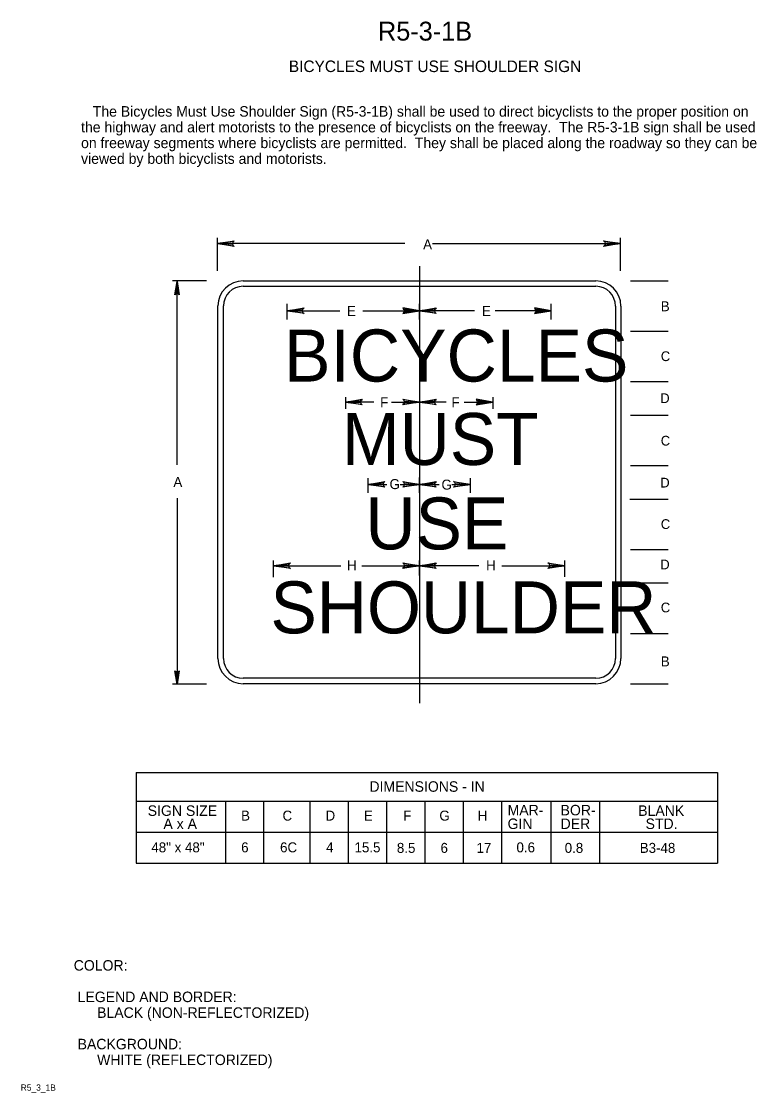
# Model space of a CAD drawing. Extents: x 0.013 to 0.188, y 0.004 to 0.259.
import ezdxf

# ---------------------------------------------------------------- set-up
doc = ezdxf.new("R2010")
doc.units = 0
for name, color, linetype in [('1', 7, 'Continuous'), ('11', 7, 'Continuous'), ('2', 7, 'Continuous'), ('3', 7, 'Continuous')]:
    doc.layers.add(name, color=color, linetype=linetype)

# ---------------------------------------------------------------- blocks, each defined once
blk = doc.blocks.new('RARROW')
at = {"layer": '3'}
for p, q in [((-2.156, 0.28500000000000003), (-2.2665, 0.384625)), ((-2.2665, 0.384625), (0, 0)), ((0, 0), (-2.2665, -0.379125)), ((-2.156, 0.28500000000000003), (-2.075625, 0.12075)), ((0, 0), (-2.156, 0.28500000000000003)), ((-2.14975, -0.2705), (0, 0)), ((-2.075625, 0.12075), (0, 0)), ((0, 0), (-2.074, -0.108)), ((-2.2665, -0.379125), (-2.14975, -0.2705)), ((-2.074, -0.108), (-2.14975, -0.2705))]:
    blk.add_line(p, q, dxfattribs=at)

msp = doc.modelspace()

# ---------------------------------------------------------------- linework, layer by layer
at = {"layer": '11'}
msp.add_line((0.059375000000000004, 0.107375), (0.059375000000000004, 0.107375), dxfattribs=at)
at = {"layer": '3'}
for p, q in [((0.059375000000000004, 0.19975), (0.059375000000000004, 0.207625)), ((0.155375, 0.19975), (0.155375, 0.207625)), ((0.10400000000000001, 0.20625000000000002), (0.059375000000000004, 0.20625000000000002)), ((0.110625, 0.20625000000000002), (0.155375, 0.20625000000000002)), ((0.1075, 0.200875), (0.1075, 0.09675)), ((0.05675, 0.197375), (0.048625, 0.197375)), ((0.04975, 0.1535), (0.04975, 0.197375)), ((0.06550000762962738, 0.197375), (0.1495, 0.197375)), ((0.15775, 0.197375), (0.16675, 0.197375)), ((0.06550000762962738, 0.19607499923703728), (0.1495, 0.19607499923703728)), ((0.076, 0.18812500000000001), (0.076, 0.19187500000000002)), ((0.1075, 0.18812500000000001), (0.1075, 0.19187500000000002)), ((0.138875, 0.18812500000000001), (0.138875, 0.19187500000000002)), ((0.05950001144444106, 0.107375), (0.05950001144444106, 0.19138392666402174)), ((0.06080001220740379, 0.107375), (0.06080001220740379, 0.19138392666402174)), ((0.076, 0.19025), (0.0885, 0.19025)), ((0.094, 0.19025), (0.1075, 0.19025)), ((0.120625, 0.19025), (0.1075, 0.19025)), ((0.138875, 0.19025), (0.1255, 0.19025)), ((0.15419999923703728, 0.19137500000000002), (0.15419999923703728, 0.107375)), ((0.1555, 0.19137500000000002), (0.1555, 0.107375)), ((0.15775, 0.185375), (0.16675, 0.185375)), ((0.15775, 0.173375), (0.16675, 0.173375)), ((0.089875, 0.169625), (0.089875, 0.166875)), ((0.096625, 0.1685), (0.089875, 0.1685)), ((0.100875, 0.1685), (0.1075, 0.1685)), ((0.1075, 0.169625), (0.1075, 0.166875)), ((0.113875, 0.1685), (0.1075, 0.1685)), ((0.11812500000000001, 0.1685), (0.125, 0.1685)), ((0.125, 0.169625), (0.125, 0.166875)), ((0.15775, 0.165375), (0.16675, 0.165375)), ((0.15775, 0.153375), (0.16675, 0.153375)), ((0.09525, 0.146875), (0.09525, 0.150375)), ((0.09525, 0.148875), (0.09973939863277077, 0.148875)), ((0.10287500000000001, 0.148875), (0.11221179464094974, 0.148875)), ((0.1075, 0.146875), (0.1075, 0.1505)), ((0.11525, 0.148875), (0.11962500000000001, 0.148875)), ((0.11962500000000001, 0.146875), (0.11962500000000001, 0.150375)), ((0.04975, 0.145625), (0.04975, 0.101375)), ((0.15762500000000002, 0.145375), (0.16675, 0.145375)), ((0.15775, 0.133375), (0.16675, 0.133375)), ((0.07275, 0.12675), (0.07275, 0.13075)), ((0.1075, 0.12712500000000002), (0.1075, 0.13075)), ((0.142125, 0.12687500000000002), (0.142125, 0.13075)), ((0.07275, 0.1295), (0.08875, 0.1295)), ((0.09375, 0.1295), (0.1075, 0.1295)), ((0.121625, 0.1295), (0.1075, 0.1295)), ((0.12712500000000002, 0.1295), (0.142125, 0.1295)), ((0.15775, 0.12537500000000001), (0.16675, 0.12537500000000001)), ((0.15775, 0.113375), (0.16675, 0.113375)), ((0.1495, 0.10267500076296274), (0.06550001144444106, 0.10267500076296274)), ((0.05675, 0.10125), (0.048625, 0.10125)), ((0.1495, 0.101375), (0.06550001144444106, 0.101375)), ((0.15775, 0.101375), (0.16675, 0.101375)), ((0.04, 0.08025), (0.1785, 0.08025)), ((0.04, 0.08025), (0.04, 0.058625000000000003)), ((0.1785, 0.08025), (0.1785, 0.058625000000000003)), ((0.04, 0.073375), (0.1785, 0.073375)), ((0.06129158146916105, 0.07337213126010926), (0.06129158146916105, 0.058622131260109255)), ((0.07037500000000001, 0.073375), (0.07037500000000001, 0.058625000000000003)), ((0.081375, 0.073375), (0.081375, 0.058625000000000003)), ((0.0905, 0.073375), (0.0905, 0.058625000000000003)), ((0.099625, 0.073375), (0.099625, 0.058625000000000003)), ((0.10875, 0.073375), (0.10875, 0.058625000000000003)), ((0.11787500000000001, 0.073375), (0.11787500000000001, 0.058625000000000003)), ((0.12704158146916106, 0.07337213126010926), (0.12704158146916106, 0.058622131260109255)), ((0.13879158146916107, 0.07337213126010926), (0.13879158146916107, 0.058622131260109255)), ((0.15041658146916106, 0.07337213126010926), (0.15041658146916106, 0.058622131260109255)), ((0.04, 0.066), (0.1785, 0.066)), ((0.04, 0.058625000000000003), (0.1785, 0.058625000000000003))]:
    msp.add_line(p, q, dxfattribs=at)
for centre, radius, start, end in [((0.06550000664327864, 0.19137499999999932), 0.006, 90, 179.9147384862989), ((0.1495, 0.19137500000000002), 0.006, 0, 90), ((0.06550000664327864, 0.19137499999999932), 0.0047, 90, 179.9147384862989), ((0.1495, 0.19137500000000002), 0.0047, 0, 90), ((0.06550001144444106, 0.107375), 0.006, 180, 270), ((0.06550001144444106, 0.107375), 0.0047, 180, 270), ((0.1495, 0.107375), 0.006, 270, 0), ((0.1495, 0.107375), 0.0047, 270, 0)]:
    msp.add_arc(centre, radius, start, end, dxfattribs=at)

# ---------------------------------------------------------------- block references
for p, xscale, yscale, rotation in [((0.059375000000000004, 0.20625000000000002), 0.0017647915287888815, 0.0017457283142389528, 180), ((0.04975, 0.19725), 0.0014118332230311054, 0.0013965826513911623, 90), ((0.076, 0.19025), 0.0017647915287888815, 0.0017457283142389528, 180), ((0.1075, 0.19025), 0.0017647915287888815, 0.0017457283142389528, 180), ((0.089875, 0.1685), 0.0017647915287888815, 0.0017457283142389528, 180), ((0.1075, 0.1685), 0.0017647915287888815, 0.0017457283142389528, 180), ((0.09525, 0.148875), 0.0017647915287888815, 0.0017457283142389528, 180), ((0.1075, 0.148875), 0.0017647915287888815, 0.0017457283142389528, 180), ((0.07275, 0.1295), 0.0017647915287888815, 0.0017457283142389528, 180), ((0.1075, 0.1295), 0.0017647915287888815, 0.0017457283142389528, 180), ((0.04975, 0.10125), 0.0014118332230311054, 0.0013965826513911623, -90)]:
    msp.add_blockref('RARROW', p, dxfattribs=dict(at, xscale=xscale, yscale=yscale, rotation=rotation))
at = {"layer": '3', "xscale": 0.0017647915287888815}
for p, yscale in [((0.155375, 0.20625000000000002), 0.0017457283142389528), ((0.1075, 0.19025), -0.0017457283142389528), ((0.138875, 0.19025), -0.0017457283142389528), ((0.1075, 0.1685), 0.0017457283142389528), ((0.125, 0.1685), -0.0017457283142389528), ((0.1075, 0.148875), 0.0017457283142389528), ((0.11962500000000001, 0.148875), 0.0017457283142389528), ((0.1075, 0.1295), 0.0017457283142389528), ((0.142125, 0.1295), 0.0017457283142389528)]:
    msp.add_blockref('RARROW', p, dxfattribs=dict(at, yscale=yscale))

# ---------------------------------------------------------------- texts
at = {"layer": '1'}
for s, height, p in [('R5-3-1B', 0.0045000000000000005, (0.097625, 0.254625)), ('BICYCLES MUST USE SHOULDER SIGN', 0.00275025, (0.076375, 0.247125)), ('COLOR:', 0.0024997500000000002, (0.025125, 0.033)), (' LEGEND AND BORDER:', 0.0024997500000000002, (0.025125, 0.025500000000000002)), ('      BLACK (NON-REFLECTORIZED)', 0.0024997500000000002, (0.025125, 0.021750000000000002)), (' BACKGROUND:', 0.0024997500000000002, (0.025125, 0.01425)), ('      WHITE (REFLECTORIZED)', 0.0024997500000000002, (0.025125, 0.0105)), ('R5_3_1B', 0.0015, (0.0125, 0.004375))]:
    msp.add_text(s, height=height, dxfattribs=at).set_placement(p)
at = {"layer": '11'}
for s, height, p in [('BICYCLES', 0.012402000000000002, (0.07525, 0.173375)), ('MUST', 0.012375, (0.089, 0.1535)), ('USE', 0.012375, (0.094625, 0.133375)), ('SHOULDER', 0.012375, (0.07200000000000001, 0.113375))]:
    msp.add_text(s, height=height, dxfattribs=at).set_placement(p)
at = {"layer": '2'}
for s, p in [('   The Bicycles Must Use Shoulder Sign (R5-3-1B) shall be used to direct bicyclists to the proper position on', (0.026875, 0.23650000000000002)), ('the highway and alert motorists to the presence of bicyclists on the freeway.  The R5-3-1B sign shall be used', (0.026875, 0.23275)), ('on freeway segments where bicyclists are permitted.  They shall be placed along the roadway so they can be', (0.026875, 0.229)), ('viewed by both bicyclists and motorists.', (0.026875, 0.22525))]:
    msp.add_text(s, height=0.0024997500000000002, dxfattribs=at).set_placement(p)
at = {"layer": '3'}
for s, height, p in [('A', 0.0023745, (0.108375, 0.204875)), ('B', 0.0023752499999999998, (0.165, 0.19012500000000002)), ('E', 0.0023752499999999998, (0.09025, 0.189)), ('E', 0.0023752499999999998, (0.122375, 0.189)), ('C', 0.0023175, (0.165, 0.17825)), ('F', 0.0023752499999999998, (0.098125, 0.16725)), ('F', 0.0023752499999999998, (0.115125, 0.16725)), ('D', 0.0023175, (0.164875, 0.16825)), ('C', 0.0023175, (0.165, 0.15812500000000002)), ('A', 0.0023752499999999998, (0.048875, 0.14825)), ('G', 0.0023752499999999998, (0.100375, 0.14775)), ('G', 0.0023752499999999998, (0.11275, 0.147625)), ('D', 0.0023175, (0.164875, 0.148125)), ('C', 0.0023175, (0.165, 0.13825)), ('H', 0.0023752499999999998, (0.09025, 0.128375)), ('H', 0.0023752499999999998, (0.123375, 0.128375)), ('D', 0.0023175, (0.164875, 0.128625)), ('C', 0.0023175, (0.165, 0.11837500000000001)), ('B', 0.0023752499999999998, (0.165, 0.1055)), ('DIMENSIONS - IN', 0.0024997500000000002, (0.09557561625, 0.075625)), ('SIGN SIZE', 0.0024997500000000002, (0.04275, 0.069875)), ('MAR-', 0.0024997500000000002, (0.1285, 0.07)), ('BOR-', 0.0024997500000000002, (0.141125, 0.07)), ('BLANK', 0.0024997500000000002, (0.15962500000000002, 0.069875)), ('A x A', 0.0024997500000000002, (0.0465, 0.06675)), ('B', 0.0023752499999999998, (0.065, 0.06875)), ('C', 0.0023752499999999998, (0.074875, 0.06875)), ('D', 0.0023752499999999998, (0.085125, 0.06875)), ('E', 0.0023752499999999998, (0.09425, 0.06875)), ('F', 0.0023752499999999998, (0.10362500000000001, 0.06875)), ('G', 0.0023752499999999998, (0.11225, 0.06875)), ('H', 0.0023752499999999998, (0.121375, 0.06875)), ('GIN', 0.0024997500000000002, (0.1285, 0.06675)), ('DER', 0.0024997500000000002, (0.141125, 0.06675)), ('STD.', 0.0024997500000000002, (0.161375, 0.06675)), ('48" x 48"', 0.0023752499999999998, (0.043620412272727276, 0.061187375)), ('6', 0.0023752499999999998, (0.06502206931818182, 0.061187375)), ('6C', 0.0023752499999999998, (0.07428957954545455, 0.061187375)), ('4', 0.0023752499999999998, (0.08526055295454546, 0.061187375)), ('15.5', 0.0023752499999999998, (0.09202661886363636, 0.061187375)), ('8.5', 0.0023752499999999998, (0.1021213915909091, 0.061062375)), ('6', 0.0023752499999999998, (0.11252206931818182, 0.061062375)), ('17', 0.0023752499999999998, (0.12108792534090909, 0.061062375)), ('0.6', 0.0023752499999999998, (0.1306185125, 0.061187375)), ('0.8', 0.0023752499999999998, (0.1421055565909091, 0.061062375)), ('B3-48', 0.0023752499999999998, (0.15998846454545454, 0.061062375))]:
    msp.add_text(s, height=height, dxfattribs=at).set_placement(p)

doc.saveas('drawing.dxf')
